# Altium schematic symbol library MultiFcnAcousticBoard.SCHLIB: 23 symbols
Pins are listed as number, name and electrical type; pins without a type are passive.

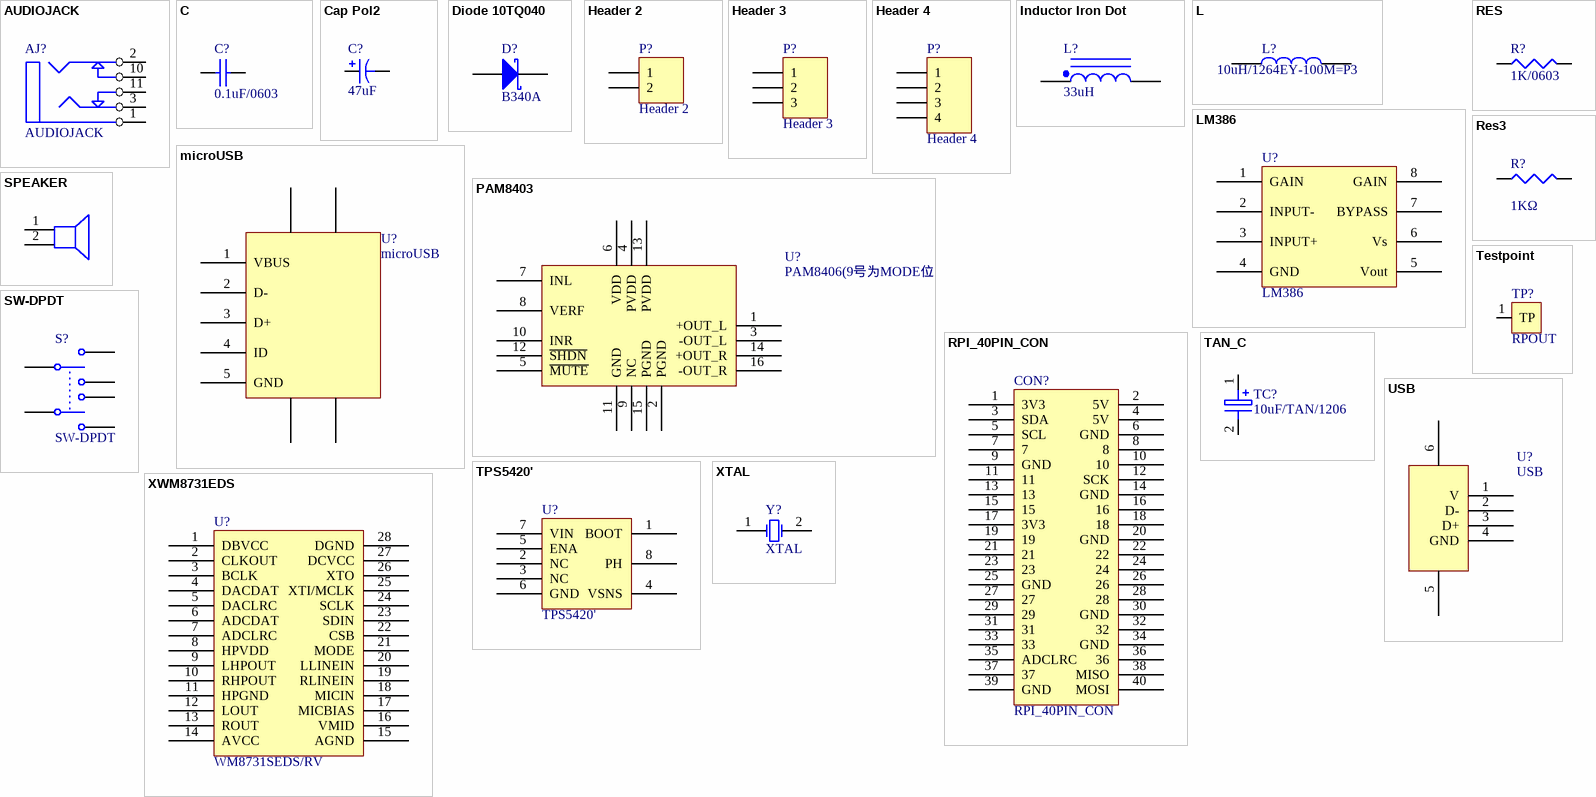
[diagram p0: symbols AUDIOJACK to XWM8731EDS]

## AUDIOJACK
designator AJ?
footprint PJ-325C
pins: 1, 2, 3, 10, 11

## C
designator C?, comment 0.1uF/0603
footprint C0603
pins: 1, 2

## Cap Pol2
designator C?, comment 47uF
Polarized Capacitor (Axial)
footprint TAN A
simulation model CAP (Capacitor)
signal-integrity model Cap Pol
pins: 1, 2
1 alternate drawing of the same symbol

## Diode 10TQ040
designator D?, comment B340A
Schottky Rectifier; Note: Terminal 2 is the TAB and is electrically connected to the cathode
footprint DIODE-SMA
simulation model 10TQ040 (DIODE)
pins: 1 K, 3 A

## Header 2
designator P?
Header, 2-Pin
footprint HDR1X2 (Connector; Header; 2 Position)
signal-integrity model Connector
pins: 1, 2

## Header 3
designator P?
Header, 3-Pin
footprint DC-005 (DC母座5.5mm)
signal-integrity model Connector
pins: 1, 2, 3

## Header 4
designator P?
Header, 4-Pin
footprint HDR1X4 (Connector; Header; 4 Position)
signal-integrity model Connector
pins: 1, 2, 3, 4

## Inductor Iron Dot
designator L?, comment 33uH
Magnetic-Core Inductor with Winding Polarity Marking
footprint INDUCTOR
signal-integrity model Inductor Iron Dot
pins: 1, 2

## L
designator L?, comment 10uH/1264EY-100M=P3
footprint INDUCTOR
pins: 1, 2

## LM386
designator U?
footprint SOIC-8 (SOIC, 8-Leads, Body 5.0x4.0mm (max), Pitch 1.27mm, IPC Medium Density)
pins: 1 GAIN, 2 INPUT-, 3 INPUT+, 4 GND, 5 Vout, 6 Vs, 7 BYPASS, 8 GAIN

## microUSB
designator U?
footprint MICRO-USB-A18
pins: 1 VBUS, 2 D-, 3 D+, 4 ID, 5 GND, 7, ?1 6, ?2 8, ?3 9

## PAM8403
designator U?, comment PAM8406(9号为MODE位)
PAM8403
footprint SOIC-16_150MIL
pins: 1 +OUT_L, 2 PGND, 3 -OUT_L, 4 PVDD, 5 ~{MUTE}, 6 VDD, 7 INL, 8 VERF, 9 NC, 10 INR, 11 GND, 12 ~{SHDN}, 13 PVDD, 14 +OUT_R, 15 PGND, 16 -OUT_R

## RES
designator R?, comment 1K/0603
footprint R0603
pins: 1, 2

## Res3
designator R?  value 1KΩ
Resistor
footprint R0603
footprint 14-1210 (Chip Resistor, Body 3.2x2.5mm, IPC High Density)
footprint 12Z-2010 (Chip Resistor, Body 5.0x2.5mm, IPC High Density)
footprint RESC6332 (Chip Resistor, Body 6.3x3.2mm, IPC High Density)
simulation model RESISTOR (Resistor)
signal-integrity model Res
pins: 1, 2

## RPI_40PIN_CON
designator CON?
footprint HDR2X20 (Connector; Header; 20x2 Position)
pins: 1 3V3, 2 5V, 3 SDA, 4 5V, 5 SCL, 6 GND, 7, 8, 9 GND, 10, 11, 12 SCK, 13, 14 GND, 15, 16, 17 3V3, 18, 19, 20 GND, 21, 22, 23, 24, 25 GND, 26, 27, 28, 29, 30 GND, 31, 32, 33, 34 GND, 35 ADCLRC, 36, 37, 38 MISO, 39 GND, 40 MOSI

## SPEAKER
designator SPEAKER?
footprint HDR1X2 (Connector; Header; 2 Position)
pins: 1, 2

## SW-DPDT
designator S?
Double-Pole, Double-Throw Switch
footprint DPDT-6 (Switch; 6 Leads)
pins: 1, 2, 3, 4, 5, 6

## TAN_C
designator TC?, comment 10uF/TAN/1206
footprint TAN_A
footprint RB.1/.2A
footprint RB.2/.4
footprint CD4
pins: 1, 2 E

## Testpoint
designator TP?, comment RPOUT
footprint TP
footprint SIP1
pins: 1 TP

## TPS5420'
designator U?
footprint SOIC-8 (SOIC, 8-Leads, Body 5.0x4.0mm (max), Pitch 1.27mm, IPC Medium Density)
pins: 1 BOOT, 2 NC, 3 NC, 4 VSNS, 5 ENA, 6 GND, 7 VIN, 8 PH

## USB
designator U?
footprint USB_A1
pins: 1 V, 2 D-, 3 D+, 4 GND, 5, 6

## XTAL
designator Y?
Crystal Oscillator
footprint R38 (Crystal, Thru-Hole; 2 Leads; Body 3.1 x 8.2 mm (Dia.xH))
simulation model XTAL (Spice Subcircuit)
pins: 1 OSC1, 2 OSC2

## XWM8731EDS
designator U?, comment WM8731SEDS/RV
footprint SSOP-28_208MIL
pins: 1 DBVCC, 2 CLKOUT, 3 BCLK, 4 DACDAT, 5 DACLRC, 6 ADCDAT, 7 ADCLRC, 8 HPVDD, 9 LHPOUT, 10 RHPOUT, 11 HPGND, 12 LOUT, 13 ROUT, 14 AVCC, 15 AGND, 16 VMID, 17 MICBIAS, 18 MICIN, 19 RLINEIN, 20 LLINEIN, 21 MODE, 22 CSB, 23 SDIN, 24 SCLK, 25 XTI/MCLK, 26 XTO, 27 DCVCC, 28 DGND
